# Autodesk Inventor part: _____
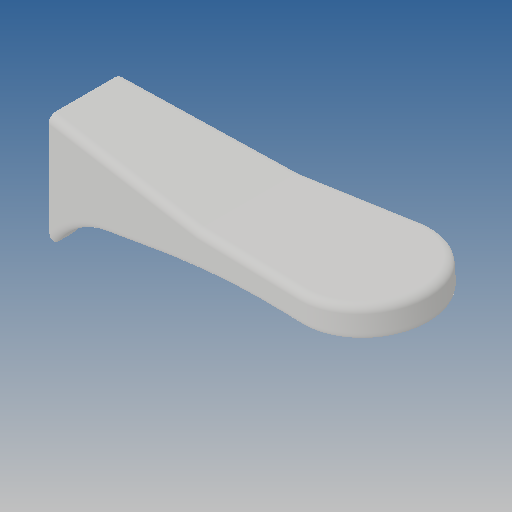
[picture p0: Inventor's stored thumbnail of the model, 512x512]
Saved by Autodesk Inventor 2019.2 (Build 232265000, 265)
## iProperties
Created: 2010-06
Part Number: _____
Material: Ogólny
Document SubType Name: Modeling
Designer: CADENGINEERING4
Density: 1 g/cm^3
Appearance: Domyślna
Author: CADENGINEERING4
Revision Number: ANY
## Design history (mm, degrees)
feature "NONE"
node "Bryła1"
